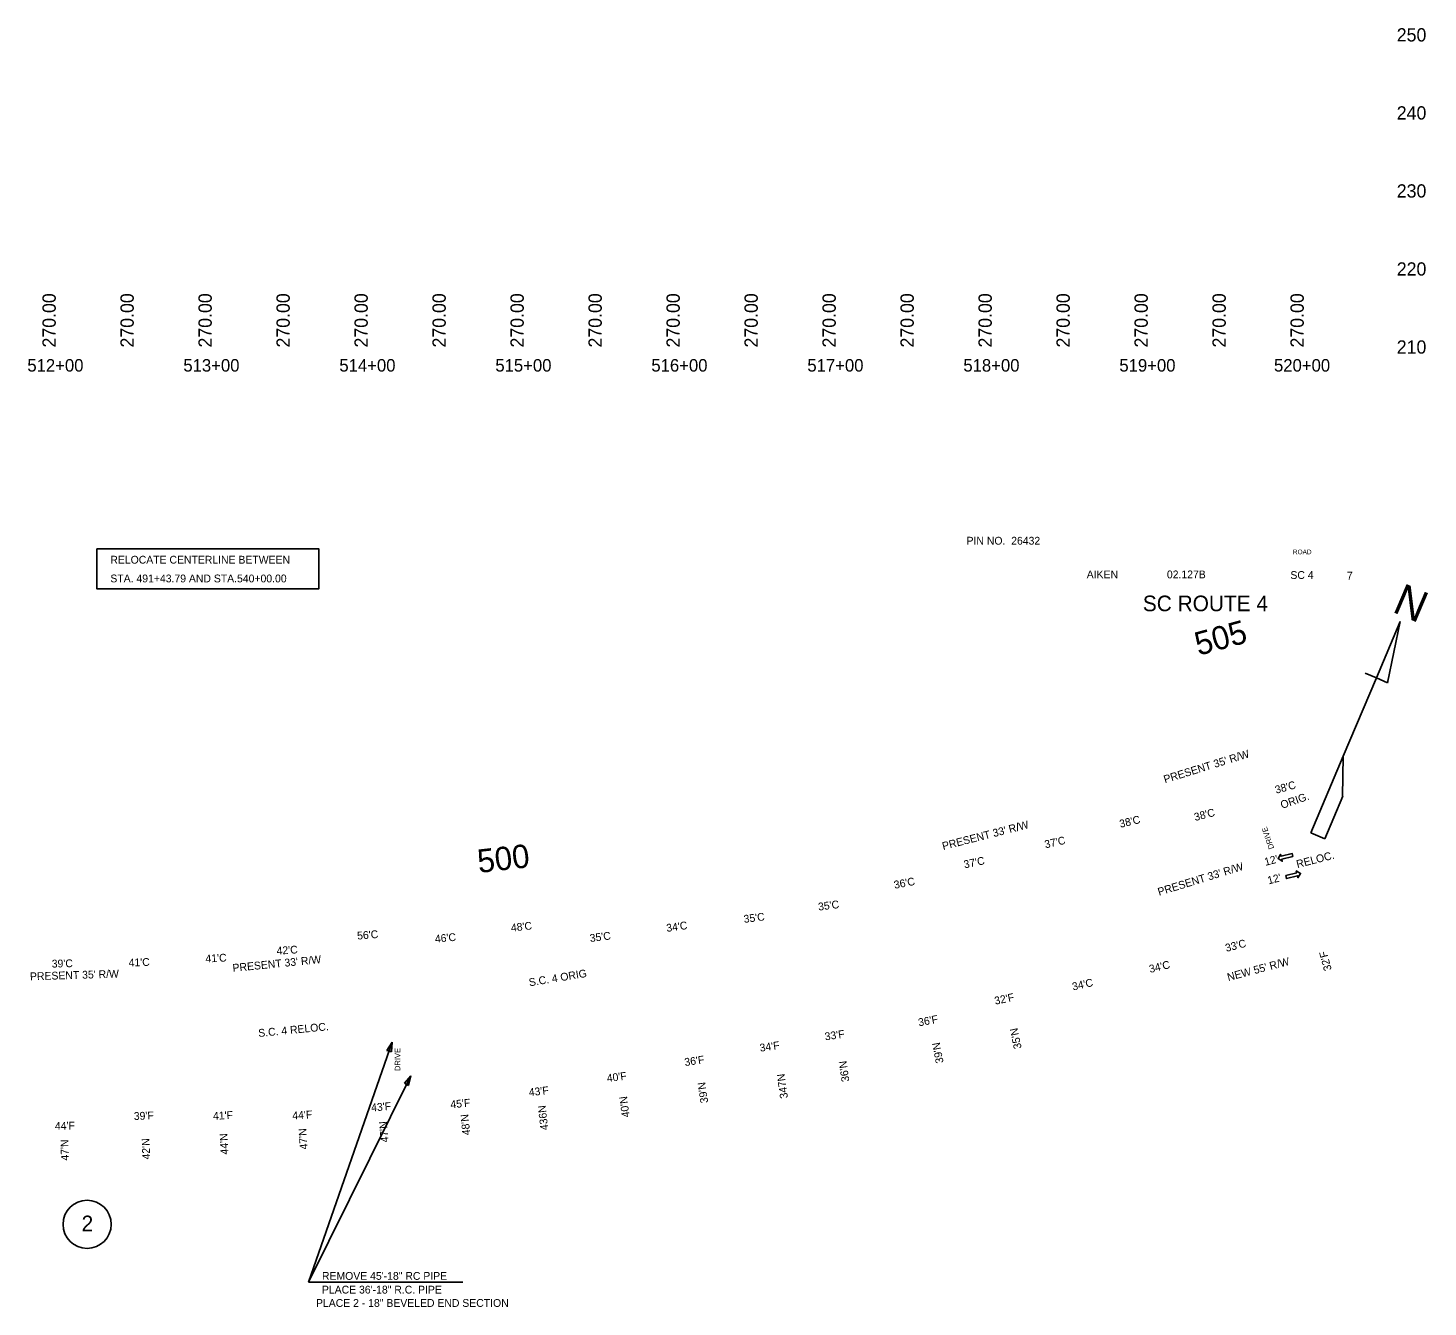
# Model space of a CAD drawing. Extents: x 48556 to 51363, y 45290 to 53458.
# Drawn here: x 49868 to 50765, y 47215 to 48034 of the extents above; entities that cross this region are included whole.
import ezdxf

# ---------------------------------------------------------------- set-up
doc = ezdxf.new("R2010")
doc.units = 0
for name, color, linetype in [('Level 1', 7, 'Continuous'), ('Level 12', 7, 'Continuous'), ('Level 14', 7, 'Continuous'), ('Level 19', 7, 'Continuous'), ('Level 2', 7, 'Continuous'), ('Level 20', 7, 'Continuous'), ('Level 21', 7, 'Continuous'), ('Level 24', 7, 'Continuous'), ('Level 29', 7, 'Continuous'), ('Level 33', 7, 'Continuous'), ('Level 39', 7, 'Continuous'), ('Level 42', 7, 'Continuous'), ('Level 43', 7, 'Continuous'), ('Level 48', 7, 'Continuous'), ('Level 6', 7, 'Continuous'), ('Level 8', 7, 'Continuous')]:
    doc.layers.add(name, color=color, linetype=linetype)

msp = doc.modelspace()

# ---------------------------------------------------------------- linework, layer by layer
at = {"layer": 'Level 12'}
msp.add_circle((49905.73, 47267.49), 15.42, dxfattribs=at)
at = {"layer": 'Level 14'}
for points in [[(50678.67, 47503.2), (50678.21, 47505.06), (50671.09, 47503.28), (50670.77, 47504.54), (50669.13, 47501.79), (50671.88, 47500.15), (50671.56, 47501.41)], [(50674.04, 47490.92), (50674.51, 47489.06), (50681.63, 47490.85), (50681.94, 47489.59), (50683.59, 47492.33), (50680.84, 47493.97), (50681.16, 47492.71)]]:
    msp.add_lwpolyline(points, close=True, dxfattribs=at)
at = {"layer": 'Level 2'}
for p, q in [((50747.5, 47653.66), (50732.19, 47617.58)), ((50739.4, 47614.52), (50747.5, 47653.66)), ((50747.5, 47653.66), (50747.5, 47653.66)), ((50710.93, 47567.51), (50732.19, 47617.58)), ((50724.97, 47620.64), (50732.19, 47617.58)), ((50732.19, 47617.58), (50739.4, 47614.52)), ((50739.4, 47614.52), (50739.59, 47614.94)), ((50710.93, 47567.51), (50690.07, 47518.35)), ((50710.57, 47541.58), (50710.93, 47567.51)), ((50699.09, 47514.52), (50710.68, 47541.83)), ((50710.68, 47541.83), (50710.57, 47541.58)), ((50690.07, 47518.35), (50699.09, 47514.52))]:
    msp.add_line(p, q, dxfattribs=at)
at = {"layer": 'Level 24'}
for p, q in [((50101.32, 47384.14), (50097.92, 47378.97)), ((50097.92, 47378.97), (50100.76, 47377.98)), ((50100.76, 47377.98), (50101.32, 47384.14)), ((50113.18, 47362.57), (50109.17, 47357.86)), ((50109.17, 47357.86), (50111.85, 47356.53)), ((50111.85, 47356.53), (50113.18, 47362.57))]:
    msp.add_line(p, q, dxfattribs=at)
at = {"layer": 'Level 6'}
for p in [(50101.32, 47384.14), (50113.18, 47362.57), (50146.58, 47230.37)]:
    msp.add_line(p, (50047.6, 47230.37), dxfattribs=at)
msp.add_lwpolyline([(49912.07, 47700.35), (50054.2, 47700.35), (50054.2, 47674.63), (49912.07, 47674.63)], close=True, dxfattribs=at)

# ---------------------------------------------------------------- texts
at = {"layer": 'Level 1'}
for s, rotation, p in [("PRESENT 35' R/W ", 17.10463, (50596.7, 47550.08)), ('ORIG.', 18.95088, (50671.7, 47533.66)), ("PRESENT 33' R/W ", 14.35389, (50454.55, 47507.28)), ('RELOC.', 14.35869, (50681.58, 47495.73)), ("PRESENT 33' R/W ", 17.10463, (50592.91, 47477.95)), ("PRESENT 33' R/W ", 5.68998, (49999.22, 47429.24)), ("PRESENT 35' R/W ", 1.74037, (49869.18, 47423.85))]:
    msp.add_text(s, height=5, rotation=rotation, dxfattribs=at).set_placement(p)
at = {"layer": 'Level 12'}
msp.add_text('2', height=10, dxfattribs=at).set_placement((49902.21, 47263.1))
at = {"layer": 'Level 19'}
for s, rotation, p in [('505', 15.24612, (50618.13, 47631.73)), ('500', 6.49615, (50156.79, 47492.58))]:
    msp.add_text(s, height=15, rotation=rotation, dxfattribs=at).set_placement(p)
at = {"layer": 'Level 2'}
msp.add_text('N', height=20, rotation=337, dxfattribs=at).set_placement((50741.69, 47660.16))
at = {"layer": 'Level 20'}
for p in [(50661.11, 47497.16), (50663.1, 47485.27)]:
    msp.add_text("12'", height=5, rotation=14.73599, dxfattribs=at).set_placement(p)
at = {"layer": 'Level 21'}
msp.add_text('S.C. 4 ORIG', height=5, rotation=9.29937, dxfattribs=at).set_placement((50189.34, 47419.98))
at = {"layer": 'Level 24'}
for s, height, p in [('PIN NO.  26432', 5, (50469.47, 47702.98)), ('ROAD', 3, (50678.66, 47696.81)), ('AIKEN', 5, (50546.51, 47681.4)), ('02.127B', 5, (50597.9, 47681.4)), ('SC 4', 5, (50677.06, 47681.01)), ('7', 5, (50713.29, 47680.61)), ('SC ROUTE 4', 10, (50582.48, 47660.32))]:
    msp.add_text(s, height=height, dxfattribs=at).set_placement(p)
at = {"layer": 'Level 29'}
for s, p in [('PLACE 36\'-18" R.C. PIPE', (50056.27, 47223.16)), (' PLACE 2 - 18" BEVELED END SECTION', (50050.61, 47214.62))]:
    msp.add_text(s, height=5, dxfattribs=at).set_placement(p)
at = {"layer": 'Level 33'}
msp.add_text("NEW 55' R/W", height=5, rotation=14.80677, dxfattribs=at).set_placement((50637.28, 47423.34))
at = {"layer": 'Level 39'}
msp.add_text('S.C. 4 RELOC.', height=5, rotation=5.55017, dxfattribs=at).set_placement((50015.69, 47387.51))
at = {"layer": 'Level 42'}
for s, height, p in [('250', 8.5, (50745.25, 48025.35)), ('240', 8.5, (50745.25, 47975.35)), ('230', 8.5, (50745.25, 47925.35)), ('220', 8.5, (50745.25, 47875.35)), ('210', 8.5, (50745.25, 47825.35)), ('512+00', 8, (49867.42, 47813.85)), ('513+00', 8, (49967.42, 47813.85)), ('514+00', 8, (50067.42, 47813.85)), ('515+00', 8, (50167.42, 47813.85)), ('516+00', 8, (50267.42, 47813.85)), ('517+00', 8, (50367.42, 47813.85)), ('518+00', 8, (50467.42, 47813.85)), ('519+00', 8, (50567.42, 47813.85)), ('520+00', 8, (50666.55, 47813.85))]:
    msp.add_text(s, height=height, dxfattribs=at).set_placement(p)
at = {"layer": 'Level 43'}
for p in [(49885.63, 47829.26), (49935.63, 47829.26), (49985.63, 47829.26), (50035.63, 47829.26), (50085.63, 47829.26), (50135.63, 47829.26), (50185.63, 47829.26), (50235.63, 47829.26), (50285.63, 47829.26), (50335.63, 47829.26), (50385.63, 47829.26), (50435.63, 47829.26), (50485.63, 47829.26), (50535.63, 47829.26), (50585.63, 47829.26), (50635.63, 47829.26), (50685.63, 47829.26)]:
    msp.add_text('270.00', height=8.5, rotation=90, dxfattribs=at).set_placement(p)
at = {"layer": 'Level 48'}
for s, rotation, p in [("38'C", 15.24611, (50667.93, 47543.36)), ("38'C", 13.49614, (50568.1, 47521.53)), ("38'C", 14.37114, (50616.01, 47525.87)), ("37'C", 12.62116, (50520.03, 47508.38)), ("37'C", 11.74614, (50468.23, 47495.54)), ("36'C", 10.87112, (50423.42, 47482.46)), ("35'C", 7.37114, (50374.63, 47468.46)), ("35'C", 7.37114, (50326.91, 47460.58)), ("48'C", 6.49614, (50177.7, 47454.98)), ("34'C", 8.24615, (50277.4, 47454.81)), ("56'C", 4.74616, (50079.03, 47449.9)), ("46'C", 5.62113, (50128.93, 47447.88)), ("35'C", 7.37114, (50228.27, 47448.35)), ("33'C", 14.37113, (50635.99, 47442.03)), ("41'C", 2.12117, (49932.44, 47432.65)), ("41'C", 2.9962, (49981.75, 47435.22)), ("42'C", 3.87113, (50027.38, 47440.24)), ("32'F", 105.24614, (50703.62, 47430.64)), ("39'C", 1.24618, (49883.11, 47431.99)), ("34'C", 13.49611, (50587.14, 47428.55)), ("34'C", 12.62112, (50537.74, 47417.27)), ("32'F", 11.74613, (50487.88, 47408.18)), ("36'F", 10.87112, (50438.97, 47394.31)), ("34'F", 8.24615, (50337.23, 47378.07)), ("33'F", 8.24615, (50378.92, 47385.32)), ("35'N", 101.74613, (50504.82, 47380.4)), ("36'F", 8.24615, (50289, 47368.89)), ("39'N", 100.87112, (50454.79, 47371.12)), ("36'N", 98.24615, (50394.39, 47359.15)), ("40'F", 7.37114, (50239.2, 47358.62)), ("39'N", 98.24615, (50303.9, 47345.52)), ('347N', 98.24615, (50355.02, 47348.45)), ("43'F", 6.49616, (50189.15, 47349.55)), ("40'N", 97.37114, (50253.55, 47336.39)), ("39'F", 2.12119, (49935.75, 47334.33)), ("41'F", 2.99616, (49986.56, 47334.42)), ("44'F", 3.87117, (50037.44, 47334.62)), ("43'F", 4.74614, (50088.01, 47339.78)), ("45'F", 5.62116, (50138.86, 47341.77)), ('436N', 96.49616, (50201.39, 47328.11)), ("44'F", 1.24616, (49885.13, 47328.02)), ("47'N", 94.74614, (50098.97, 47320.23)), ("48'N", 95.62116, (50151.37, 47324.82)), ("47'N", 91.24616, (49893.99, 47308.39)), ("42'N", 92.12119, (49946.18, 47309.15)), ("44'N", 92.99616, (49996.33, 47312.36)), ("47'N", 93.87117, (50047.11, 47315.64))]:
    msp.add_text(s, height=5, rotation=rotation, dxfattribs=at).set_placement(p)
at = {"layer": 'Level 6'}
for s, p in [('RELOCATE CENTERLINE BETWEEN', (49920.64, 47690.81)), ('STA. 491+43.79 AND STA.540+00.00', (49920.64, 47678.81)), ('REMOVE 45\'-18" RC PIPE', (50056.3, 47231.95))]:
    msp.add_text(s, height=5, dxfattribs=at).set_placement(p)
at = {"layer": 'Level 8'}
for rotation, p in [(108.89761, (50666.71, 47508.5)), (90, (50106.47, 47365.71))]:
    msp.add_text('DRIVE', height=3.5, rotation=rotation, dxfattribs=at).set_placement(p)

doc.saveas('drawing.dxf')
